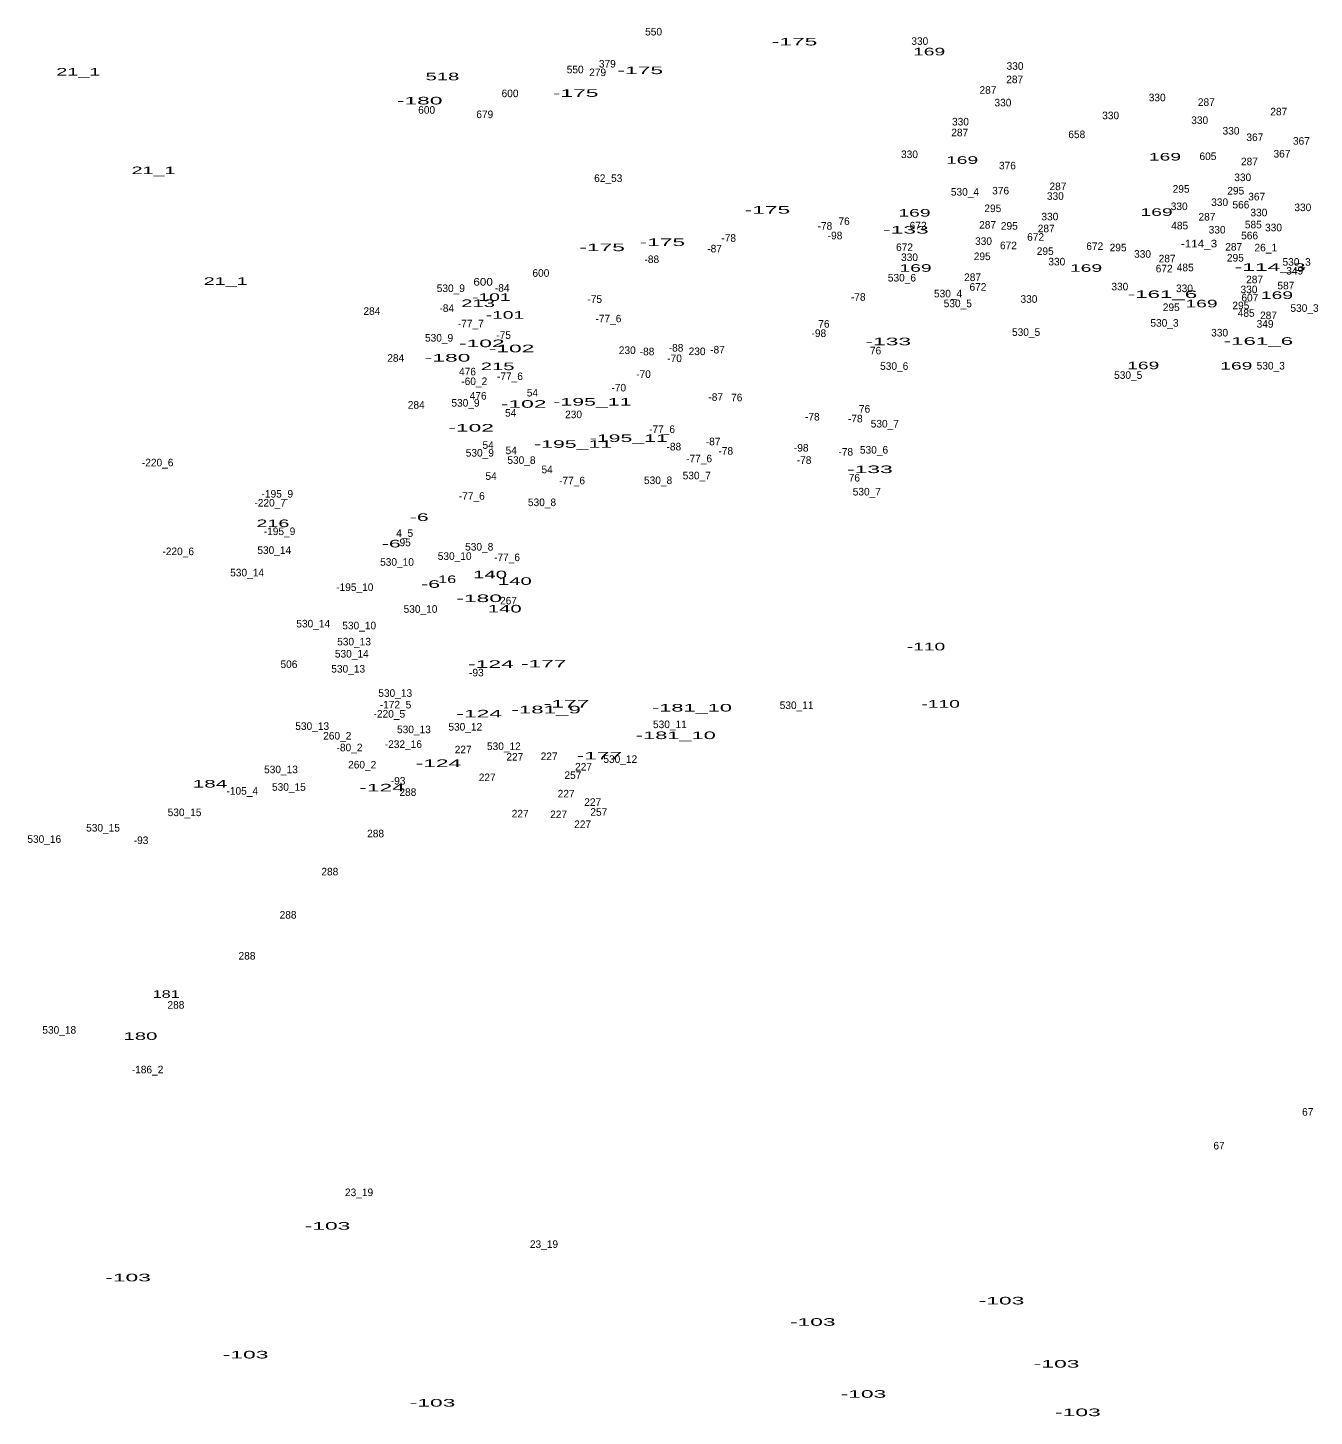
# Model space of a CAD drawing. Extents: x -661742 to -657295, y -1002932 to -996888.
# Drawn here: x -658801 to -658122, y -999109 to -998376 of the extents above; entities that cross this region are included whole.
import ezdxf
from ezdxf.enums import TextEntityAlignment as Align

# ---------------------------------------------------------------- set-up
doc = ezdxf.new("R2010")
doc.units = 0
doc.header["$LTSCALE"] = 1.6
doc.layers.add('24', color=7, linetype='Continuous')

msp = doc.modelspace()

# ---------------------------------------------------------------- texts
at = {"layer": '24'}
for s, p in [('550', (-658470.961, -998379.91)), ('330', (-658330.451, -998384.88)), ('550', (-658512.351, -998399.88)), ('379', (-658495.368, -998396.84)), ('330', (-658280.171, -998398.04)), ('279', (-658500.488, -998401.38)), ('287', (-658280.343, -998405.1)), ('600', (-658546.731, -998412.5)), ('287', (-658294.463, -998410.71)), ('330', (-658205.131, -998414.66)), ('600', (-658590.741, -998421.23)), ('330', (-658286.551, -998417.36)), ('287', (-658179.193, -998417.09)), ('287', (-658140.963, -998422.12)), ('679', (-658560.063, -998423.55)), ('330', (-658308.981, -998427.43)), ('330', (-658229.691, -998424.14)), ('330', (-658182.691, -998426.65)), ('287', (-658309.353, -998433.15)), ('658', (-658247.573, -998434.13)), ('330', (-658166.161, -998432.24)), ('367', (-658153.578, -998435.66)), ('330', (-658335.871, -998444.66)), ('367', (-658139.268, -998444.36)), ('367', (-658129.018, -998437.59)), ('376', (-658284.178, -998450.61)), ('605', (-658178.347, -998445.68)), ('287', (-658156.433, -998448.44)), ('62_53', (-658494.89, -998457.27)), ('330', (-658159.971, -998456.81)), ('530_4', (-658306.604, -998464.48)), ('376', (-658287.758, -998463.86)), ('287', (-658257.523, -998461.59)), ('295', (-658192.493, -998462.92)), ('295', (-658163.673, -998463.89)), ('295', (-658291.893, -998473.18)), ('330', (-658258.891, -998466.7)), ('330', (-658193.521, -998472.12)), ('330', (-658172.161, -998469.96)), ('566', (-658160.958, -998471.24)), ('367', (-658152.608, -998467)), ('330', (-658128.251, -998472.67)), ('76', (-658370.408, -998480)), ('330', (-658261.791, -998477.53)), ('287', (-658178.873, -998477.65)), ('330', (-658151.461, -998475.38)), ('-78', (-658380.531, -998482.46)), ('-98', (-658375.19, -998487.52)), ('672', (-658331.338, -998482.3)), ('287', (-658294.653, -998481.91)), ('295', (-658283.193, -998482.46)), ('672', (-658269.298, -998488.31)), ('287', (-658263.713, -998483.84)), ('485', (-658193.251, -998482.3)), ('330', (-658173.511, -998484.47)), ('566', (-658156.358, -998487.53)), ('585', (-658154.397, -998481.74)), ('330', (-658143.731, -998483.31)), ('-87', (-658438.761, -998494.47)), ('-78', (-658431.321, -998488.86)), ('672', (-658338.508, -998493.74)), ('330', (-658296.801, -998490.5)), ('672', (-658283.648, -998492.77)), ('295', (-658264.243, -998495.81)), ('672', (-658238.088, -998493.16)), ('295', (-658225.753, -998493.88)), ('287', (-658164.753, -998493.51)), ('26_1', (-658147.824, -998493.89)), ('-88', (-658471.895, -998500.09)), ('330', (-658335.871, -998499.01)), ('295', (-658297.503, -998498.52)), ('330', (-658258.121, -998501.33)), ('330', (-658212.861, -998497.27)), ('287', (-658199.893, -998499.71)), ('295', (-658163.863, -998499.3)), ('530_3', (-658131.529, -998501.49)), ('600', (-658530.451, -998507.33)), ('530_6', (-658339.874, -998509.82)), ('287', (-658302.583, -998509.57)), ('672', (-658201.448, -998504.99)), ('485', (-658190.341, -998504.41)), ('349', (-658132.527, -998506.15)), ('530_9', (-658577.984, -998515.37)), ('-84', (-658550.869, -998515.21)), ('672', (-658299.738, -998514.68)), ('330', (-658224.861, -998514.49)), ('330', (-658190.721, -998515.43)), ('330', (-658156.681, -998516)), ('287', (-658153.723, -998510.73)), ('587', (-658137.223, -998513.96)), ('-75', (-658502.041, -998521.12)), ('-78', (-658362.931, -998519.98)), ('530_4', (-658315.524, -998518.19)), ('530_5', (-658310.389, -998523.4)), ('330', (-658272.821, -998521.06)), ('295', (-658160.963, -998524.46)), ('607', (-658156.212, -998520.34)), ('284', (-658619.641, -998527.44)), ('-84', (-658580.139, -998525.88)), ('-77_6', (-658494.808, -998531.41)), ('295', (-658197.713, -998525.41)), ('485', (-658158.161, -998528.45)), ('287', (-658146.373, -998529.7)), ('530_3', (-658127.359, -998525.83)), ('-77_7', (-658567.439, -998534)), ('-98', (-658383.72, -998539.1)), ('76', (-658381.048, -998534.17)), ('530_5', (-658274.329, -998538.53)), ('530_3', (-658201.279, -998533.68)), ('330', (-658172.161, -998538.84)), ('349', (-658148.177, -998534.18)), ('530_9', (-658584.184, -998541.55)), ('-75', (-658550.121, -998540.12)), ('-88', (-658459.095, -998546.83)), ('284', (-658607.071, -998552.21)), ('230', (-658484.851, -998548.1)), ('-88', (-658474.415, -998548.77)), ('-70', (-658459.894, -998552.37)), ('230', (-658448.011, -998548.68)), ('-87', (-658437.221, -998547.81)), ('76', (-658353.778, -998548.3)), ('476', (-658569.183, -998559.37)), ('-77_6', (-658546.768, -998561.84)), ('-70', (-658476.274, -998560.71)), ('530_6', (-658343.944, -998556.46)), ('530_5', (-658220.429, -998561.22)), ('530_3', (-658145.189, -998556.28)), ('-60_2', (-658565.622, -998564.5)), ('-70', (-658489.354, -998567.88)), ('530_9', (-658570.234, -998575.88)), ('476', (-658563.563, -998572.17)), ('54', (-658534.891, -998570.52)), ('-87', (-658438.171, -998572.82)), ('76', (-658427.078, -998573.06)), ('284', (-658596.241, -998576.97)), ('54', (-658546.391, -998581.16)), ('230', (-658513.201, -998581.99)), ('-78', (-658387.161, -998583.22)), ('76', (-658359.578, -998579.06)), ('-77_6', (-658466.508, -998589.77)), ('-78', (-658364.481, -998584.19)), ('530_7', (-658348.904, -998586.91)), ('54', (-658558.291, -998598.19)), ('-87', (-658439.531, -998596.28)), ('530_9', (-658562.674, -998602.26)), ('54', (-658546.101, -998600.99)), ('-88', (-658460.255, -998599)), ('-77_6', (-658446.928, -998605.27)), ('-78', (-658432.871, -998601.26)), ('-98', (-658393.03, -998599.61)), ('-78', (-658369.521, -998601.74)), ('530_6', (-658354.604, -998600.68)), ('-220_6', (-658732.732, -998607.41)), ('530_8', (-658540.699, -998606.11)), ('54', (-658527.151, -998611.05)), ('-78', (-658391.521, -998606.1)), ('54', (-658556.741, -998614.54)), ('-77_6', (-658513.998, -998616.9)), ('530_8', (-658468.579, -998616.78)), ('530_7', (-658448.164, -998614.26)), ('76', (-658364.988, -998615.43)), ('-195_9', (-658669.567, -998623.93)), ('-77_6', (-658566.928, -998625.05)), ('530_7', (-658358.404, -998622.79)), ('-220_7', (-658673.332, -998628.64)), ('530_8', (-658529.849, -998628.41)), ('-195_9', (-658668.397, -998643.71)), ('4_5', (-658602.351, -998644.69)), ('95', (-658602.073, -998649.6)), ('-220_6', (-658721.882, -998654.3)), ('530_14', (-658671.177, -998653.68)), ('530_10', (-658575.957, -998656.81)), ('530_8', (-658562.999, -998651.88)), ('530_10', (-658606.387, -998659.91)), ('-77_6', (-658548.318, -998657.44)), ('530_14', (-658685.517, -998665.51)), ('-195_10', (-658628.669, -998673.22)), ('530_10', (-658593.987, -998684.74)), ('267', (-658547.538, -998680.33)), ('530_14', (-658650.627, -998692.47)), ('530_10', (-658626.357, -998693.46)), ('530_14', (-658630.267, -998708.37)), ('530_13', (-658629.053, -998701.96)), ('506', (-658663.427, -998713.9)), ('530_13', (-658632.153, -998716.31)), ('-93', (-658564.5, -998718.3)), ('530_13', (-658607.333, -998729.11)), ('-172_5', (-658607.182, -998735.25)), ('530_11', (-658395.466, -998735.55)), ('-220_5', (-658610.446, -998740.1)), ('530_13', (-658651.153, -998746.56)), ('260_2', (-658637.924, -998751.66)), ('530_13', (-658597.453, -998748.31)), ('530_12', (-658570.343, -998746.93)), ('530_11', (-658462.346, -998745.63)), ('-80_2', (-658631.456, -998757.86)), ('-232_16', (-658603.041, -998756.1)), ('227', (-658571.463, -998758.92)), ('530_12', (-658549.993, -998757.21)), ('260_2', (-658624.774, -998766.94)), ('227', (-658544.193, -998762.79)), ('227', (-658526.103, -998762.5)), ('530_12', (-658488.533, -998764)), ('530_13', (-658667.633, -998769.45)), ('227', (-658558.793, -998773.62)), ('257', (-658513.543, -998772.46)), ('227', (-658507.933, -998768.01)), ('-105_4', (-658688.064, -998780.77)), ('530_15', (-658663.463, -998778.71)), ('-93', (-658605.8, -998775.44)), ('288', (-658600.667, -998781.41)), ('227', (-658517.113, -998782.23)), ('227', (-658503.093, -998786.68)), ('530_15', (-658718.523, -998792.09)), ('227', (-658541.383, -998792.78)), ('227', (-658521.083, -998793.17)), ('257', (-658499.863, -998791.91)), ('530_15', (-658761.563, -998800.24)), ('288', (-658617.687, -998803.27)), ('227', (-658508.413, -998798.39)), ('530_16', (-658792.578, -998806.21)), ('-93', (-658741.5, -998806.83)), ('288', (-658641.857, -998823.39)), ('288', (-658663.907, -998846.22)), ('288', (-658685.567, -998867.84)), ('288', (-658723.087, -998893.77)), ('530_18', (-658784.673, -998906.97)), ('-186_2', (-658738.052, -998927.89)), ('67', (-658125.678, -998950.28)), ('67', (-658172.488, -998968.08)), ('23_19', (-658626.424, -998992.73)), ('23_19', (-658528.814, -999020.09))]:
    msp.add_text(s, height=4, dxfattribs=at).set_placement(p, align=Align.CENTER)
for s, width, p in [('-175', 2.25, (-658396.555, -998385.18)), ('169', 1.9, (-658325.517, -998390.43)), ('-175', 2.25, (-658477.975, -998400.31)), ('21_1', 1.95, (-658774.615, -998401.08)), ('518', 2, (-658582.417, -998403.58)), ('-175', 2.25, (-658512.095, -998412.33)), ('-180', 2.25, (-658594.437, -998416.33)), ('169', 1.9, (-658308.107, -998447.69)), ('169', 1.9, (-658201.027, -998445.95)), ('21_1', 1.95, (-658734.925, -998453.13)), ('-175', 2.25, (-658410.895, -998474)), ('169', 1.9, (-658333.247, -998475.55)), ('169', 1.9, (-658205.467, -998475.17)), ('-133', 2.25, (-658337.771, -998484.52)), ('-175', 2.25, (-658498.135, -998493.79)), ('-175', 2.25, (-658466.345, -998491.07)), ('-114_3', 1.15, (-658183.059, -998491.81)), ('169', 1.9, (-658332.687, -998504.68)), ('169', 1.9, (-658242.667, -998504.71)), ('-114_3', 2.25, (-658145.493, -998504.19)), ('21_1', 1.95, (-658696.845, -998511.61)), ('600', 1.15, (-658560.951, -998511.99)), ('213', 2, (-658563.577, -998523.3)), ('-101', 1.9, (-658556.613, -998520.05)), ('-161_6', 2.2, (-658202.327, -998518.52)), ('169', 1.9, (-658181.737, -998523.48)), ('169', 1.9, (-658141.897, -998519.03)), ('-101', 1.9, (-658549.433, -998529.46)), ('-102', 2.25, (-658561.647, -998544.48)), ('-102', 2.25, (-658545.937, -998547.19)), ('-133', 2.25, (-658347.071, -998543.48)), ('-161_6', 2.2, (-658151.727, -998543.25)), ('-180', 2.25, (-658579.707, -998552.09)), ('215', 2, (-658553.287, -998556.62)), ('169', 1.9, (-658212.497, -998556.14)), ('169', 1.9, (-658163.367, -998556.34)), ('-102', 2.25, (-658539.537, -998576.48)), ('-195_11', 2.1, (-658503.259, -998575.34)), ('-102', 2.25, (-658567.267, -998589.08)), ('-195_11', 2.1, (-658513.439, -998597.64)), ('-195_11', 2.1, (-658484.059, -998594.54)), ('-133', 2.25, (-658356.771, -998610.97)), ('216', 1.95, (-658671.883, -998639.5)), ('-6', 2.1, (-658594.679, -998636.25)), ('-6', 2.1, (-658609.409, -998650.22)), ('-6', 2.1, (-658588.669, -998671.55)), ('16', 1.6, (-658579.893, -998669.04)), ('140', 2, (-658557.259, -998666.52)), ('140', 2, (-658544.199, -998670)), ('-180', 2.25, (-658563.027, -998679.08)), ('140', 2, (-658549.519, -998684.57)), ('-110', 1.9, (-658327.183, -998704.58)), ('-124', 2.25, (-658556.806, -998713.81)), ('-177', 2.25, (-658528.929, -998713.61)), ('-181_9', 2.2, (-658527.683, -998737.84)), ('-177', 2.25, (-658516.909, -998734.75)), ('-181_10', 2.15, (-658450.7, -998736.87)), ('-110', 1.9, (-658319.433, -998734.84)), ('-124', 2.25, (-658563.006, -998739.98)), ('-181_10', 2.15, (-658459.23, -998751.42)), ('-124', 2.25, (-658584.526, -998766.16)), ('-177', 2.25, (-658499.579, -998762.17)), ('184', 2.05, (-658705.123, -998777.01)), ('-124', 2.25, (-658614.286, -998779.06)), ('181', 1.6, (-658728.224, -998888.04)), ('180', 2, (-658741.814, -998910.24)), ('-103', 2.25, (-658643.077, -999010.46)), ('-103', 2.25, (-658748.357, -999037.72)), ('-103', 2.25, (-658287.297, -999049.93)), ('-103', 2.25, (-658386.937, -999061.18)), ('-103', 2.25, (-658686.317, -999078.44)), ('-103', 2.25, (-658258.217, -999083.29)), ('-103', 2.25, (-658587.637, -999103.86)), ('-103', 2.25, (-658360.187, -999099.19)), ('-103', 2.25, (-658246.967, -999108.89))]:
    msp.add_text(s, height=4, dxfattribs=dict(at, width=width)).set_placement(p, align=Align.CENTER)

doc.saveas('drawing.dxf')
